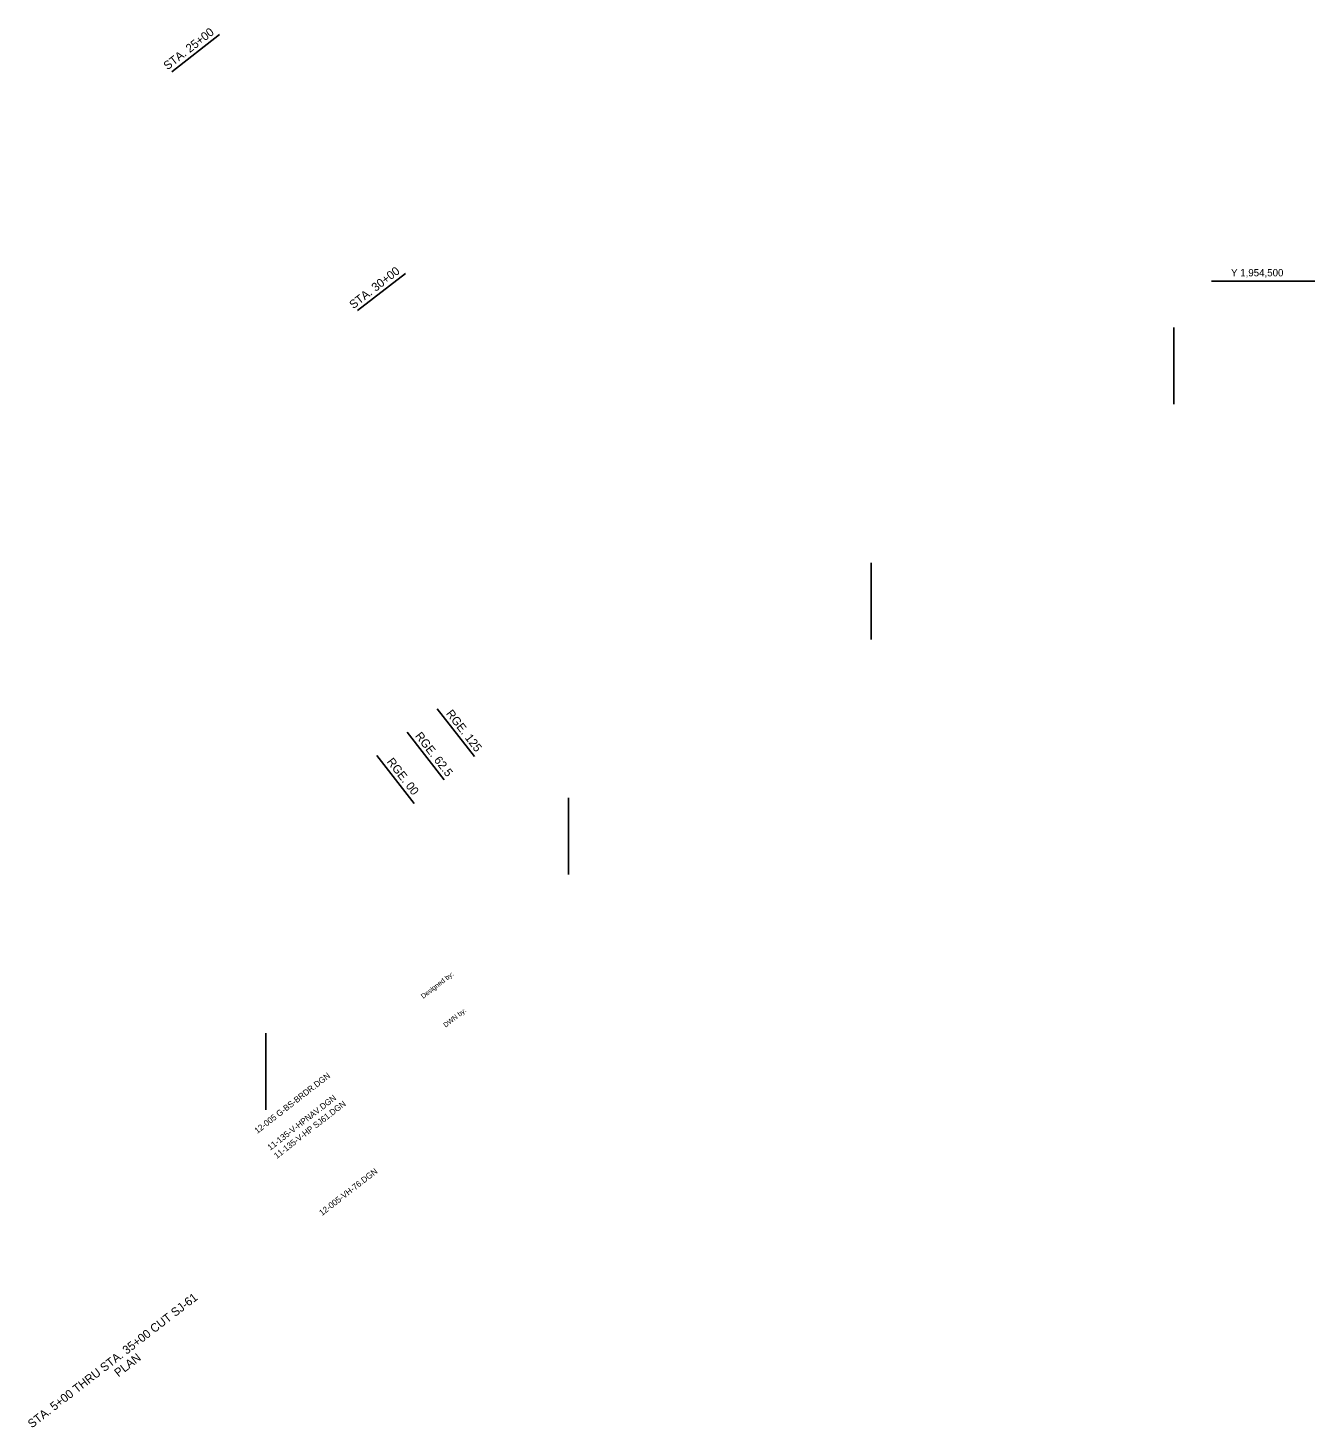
# Model space of a CAD drawing. Extents: x 576902 to 581733, y 1952373 to 1957293.
# Drawn here: x 579607 to 581733, y 1952605 to 1954918 of the extents above; entities that cross this region are included whole.
import ezdxf

# ---------------------------------------------------------------- set-up
doc = ezdxf.new("R2010")
doc.units = 0
for name, color, linetype in [('V-ANNO-DIMS', 7, 'Continuous'), ('V-ANNO-KEYN', 7, 'Continuous'), ('V-ANNO-SYMB', 7, 'Continuous'), ('V-ANNO-TEXT', 7, 'Continuous'), ('V-DUCT-MULT', 7, 'Continuous'), ('V-DUCT-MULT-IDEN', 7, 'Continuous')]:
    doc.layers.add(name, color=color, linetype=linetype)

msp = doc.modelspace()

# ---------------------------------------------------------------- linework, layer by layer
at = {"layer": 'V-ANNO-SYMB'}
for p, q in [((580283, 1953793.5), (580344.4, 1953714.5)), ((580233.2, 1953754.8), (580294.6, 1953675.9)), ((580183.5, 1953716.1), (580244.9, 1953637.2))]:
    msp.add_line(p, q, dxfattribs=at)
at = {"layer": 'V-ANNO-TEXT'}
for p, q in [((579844.7, 1954846), (579923.7, 1954907.4)), ((580151.6, 1954451.3), (580230.5, 1954512.7))]:
    msp.add_line(p, q, dxfattribs=at)
at = {"layer": 'V-DUCT-MULT-IDEN'}
for p, q in [((581561.9, 1954500), (581732.9, 1954500)), ((581500, 1954423.6), (581500, 1954296.9)), ((581000, 1954034.9), (581000, 1953908.2)), ((580500, 1953646.2), (580500, 1953519.5)), ((580000, 1953257.5), (580000, 1953130.9))]:
    msp.add_line(p, q, dxfattribs=at)

# ---------------------------------------------------------------- texts
at = {"layer": 'V-ANNO-DIMS'}
for s, p in [('Designed by:', (580260.1, 1953314.2)), ('Designed by:', (580260.1, 1953314.2)), ('Designed by:', (580260.1, 1953314.2)), ('DWN by:', (580297, 1953266.7)), ('DWN by:', (580297, 1953266.7)), ('DWN by:', (580297, 1953266.7))]:
    msp.add_text(s, height=8, rotation=37.8605, dxfattribs=at).set_placement(p)
at = {"layer": 'V-ANNO-KEYN'}
for s, height, p in [('12-005 G-BS-BRDR.DGN                ', 10, (579986, 1953091.1)), ('12-005 G-BS-BRDR.DGN                ', 10, (579986, 1953091.1)), ('11-135-V-HPNAV.DGN                  ', 10, (580007.5, 1953063.5)), ('11-135-V-HP SJ61.DGN                ', 10, (580018.2, 1953049.7)), ('12-005-VH-76.DGN                    ', 10, (580092.8, 1952955.4)), ('          STA. 5+00 THRU STA. 35+00 CUT SJ-61          ', 14, (579572.5, 1952572.6)), ('                          PLAN                         ', 14, (579649.7, 1952606))]:
    msp.add_text(s, height=height, rotation=37.8605, dxfattribs=at).set_placement(p)
at = {"layer": 'V-ANNO-SYMB'}
for s, p in [('RGE. 125', (580296.9, 1953785.4)), ('RGE. 62.5', (580245.8, 1953748.5)), ('RGE. 00', (580199.1, 1953705.8))]:
    msp.add_text(s, height=13.92, rotation=307.8605, dxfattribs=at).set_placement(p)
at = {"layer": 'V-ANNO-TEXT'}
for s, p in [('STA. 25+00', (579837.7, 1954848.2)), ('STA. 30+00', (580144.6, 1954453.5))]:
    msp.add_text(s, height=13.92, rotation=37.8605, dxfattribs=at).set_placement(p)
at = {"layer": 'V-DUCT-MULT'}
msp.add_text('Y 1,954,500', height=12, dxfattribs=at).set_placement((581594.2, 1954508))

doc.saveas('drawing.dxf')
